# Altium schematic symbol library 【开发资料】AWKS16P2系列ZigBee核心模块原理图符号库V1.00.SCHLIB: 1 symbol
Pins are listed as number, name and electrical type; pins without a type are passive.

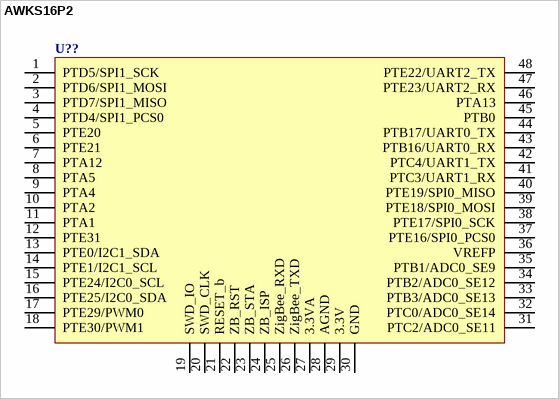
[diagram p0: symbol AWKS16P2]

## AWKS16P2
designator U??, comment AWKS16P2EF V1.00  (value not drawn)
物料代码: 80.04.00294; 名称: ZigBee模块; 贴片和直插: SMT; PCB备注: 180904lmd
footprint AW54113P2
pins: 1 PTD5/SPI1_SCK, 2 PTD6/SPI1_MOSI, 3 PTD7/SPI1_MISO, 4 PTD4/SPI1_PCS0, 5 PTE20, 6 PTE21, 7 PTA12, 8 PTA5, 9 PTA4, 10 PTA2, 11 PTA1, 12 PTE31, 13 PTE0/I2C1_SDA, 14 PTE1/I2C1_SCL, 15 PTE24/I2C0_SCL, 16 PTE25/I2C0_SDA, 17 PTE29/PWM0, 18 PTE30/PWM1, 19 SWD_IO, 20 SWD_CLK, 21 RESET_b, 22 ZB_RST, 23 ZB_STA, 24 ZB_ISP, 25 ZigBee_RXD, 26 ZigBee_TXD, 27 3.3VA, 28 AGND, 29 3.3V, 30 GND, 31 PTC2/ADC0_SE11, 32 PTC0/ADC0_SE14, 33 PTB3/ADC0_SE13, 34 PTB2/ADC0_SE12, 35 PTB1/ADC0_SE9, 36 VREFP, 37 PTE16/SPI0_PCS0, 38 PTE17/SPI0_SCK, 39 PTE18/SPI0_MOSI, 40 PTE19/SPI0_MISO, 41 PTC3/UART1_RX, 42 PTC4/UART1_TX, 43 PTB16/UART0_RX, 44 PTB17/UART0_TX, 45 PTB0, 46 PTA13, 47 PTE23/UART2_RX, 48 PTE22/UART2_TX
2 alternate drawings of the same symbol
